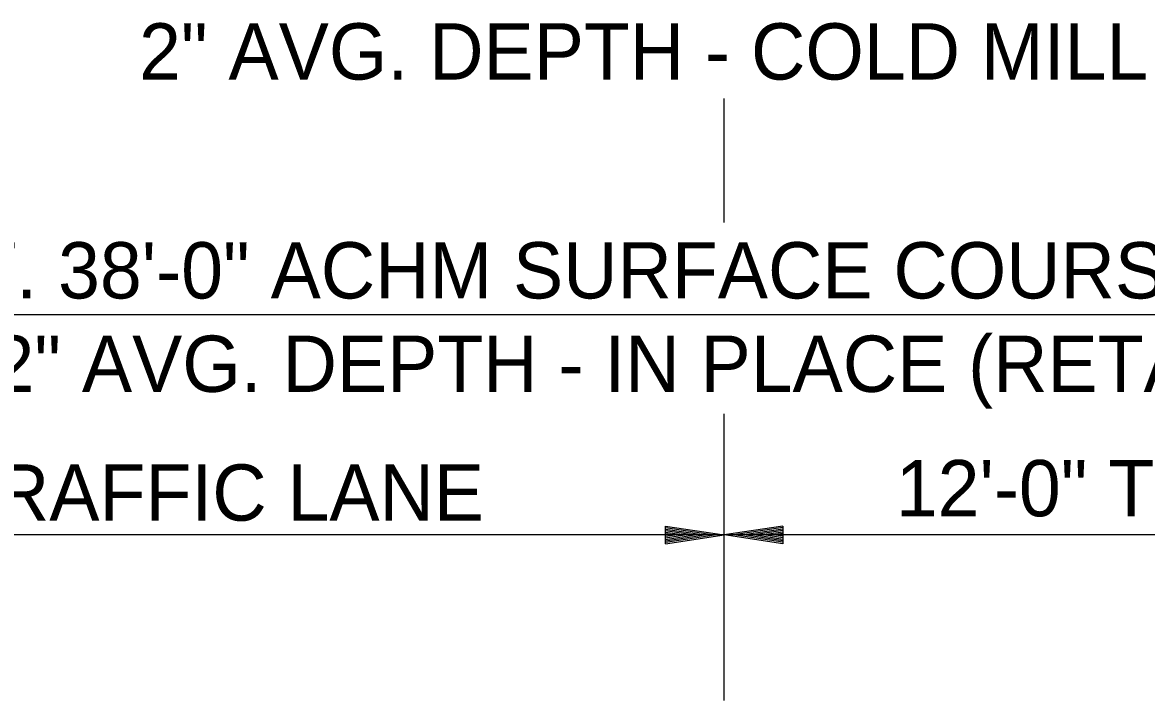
# Model space of a CAD drawing. Extents: x 1364961 to 1365294, y 367927 to 368034.
# Drawn here: x 1365036.03 to 1365047.54, y 367955.47 to 367962.41 of the extents above; entities that cross this region are included whole.
import ezdxf

# ---------------------------------------------------------------- set-up
doc = ezdxf.new("R2010")
doc.units = 0
doc.layers.add('Default', color=7, linetype='Continuous')

msp = doc.modelspace()

# ---------------------------------------------------------------- linework, layer by layer
at = {"layer": 'Default'}
for p, q in [((1365043.214, 367960.36), (1365043.214, 367961.627)), ((1365030.674, 367959.416), (1365055.792, 367959.416)), ((1365043.214, 367957.328), (1365043.214, 367958.401)), ((1365042.614, 367957.251), (1365043.214, 367957.161)), ((1365042.614, 367957.071), (1365042.614, 367957.251)), ((1365043.214, 367955.467), (1365043.214, 367957.328)), ((1365043.814, 367957.251), (1365043.214, 367957.161)), ((1365043.814, 367957.251), (1365043.814, 367957.071)), ((1365043.214, 367957.161), (1365031.225, 367957.161)), ((1365042.614, 367957.236), (1365043.114, 367957.161)), ((1365042.614, 367957.221), (1365043.011, 367957.161)), ((1365042.614, 367957.206), (1365042.911, 367957.161)), ((1365042.614, 367957.19), (1365042.809, 367957.161)), ((1365042.614, 367957.175), (1365042.709, 367957.161)), ((1365042.614, 367957.071), (1365043.214, 367957.161)), ((1365042.614, 367957.132), (1365042.809, 367957.161)), ((1365042.614, 367957.101), (1365043.011, 367957.161)), ((1365042.614, 367957.086), (1365043.114, 367957.161)), ((1365042.614, 367957.116), (1365042.911, 367957.161)), ((1365042.614, 367957.147), (1365042.709, 367957.161)), ((1365055.214, 367957.161), (1365043.214, 367957.161)), ((1365043.814, 367957.071), (1365043.214, 367957.161)), ((1365043.814, 367957.236), (1365043.314, 367957.161)), ((1365043.814, 367957.086), (1365043.314, 367957.161)), ((1365043.814, 367957.221), (1365043.417, 367957.161)), ((1365043.814, 367957.101), (1365043.417, 367957.161)), ((1365043.814, 367957.206), (1365043.517, 367957.161)), ((1365043.814, 367957.116), (1365043.517, 367957.161)), ((1365043.814, 367957.19), (1365043.619, 367957.161)), ((1365043.814, 367957.132), (1365043.619, 367957.161)), ((1365043.814, 367957.175), (1365043.719, 367957.161)), ((1365043.814, 367957.147), (1365043.719, 367957.161))]:
    msp.add_line(p, q, dxfattribs=at)

# ---------------------------------------------------------------- texts
for s, p in [('2" AVG. DEPTH - COLD MILL', (1365037.223, 367961.821)), ('EXIST. 38\'-0" ACHM SURFACE COURSE (1/2")', (1365033.74, 367959.581)), ('2" AVG. DEPTH - IN PLACE (RETAIN)', (1365035.722, 367958.625)), ('12\'-0" TRAFFIC LANE', (1365044.971, 367957.352)), ('12\'-0" TRAFFIC LANE', (1365033.101, 367957.307))]:
    msp.add_text(s, height=0.576, dxfattribs=at).set_placement(p)

doc.saveas('drawing.dxf')
